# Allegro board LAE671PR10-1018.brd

Outline 297.76 x 76 mm; copper layers: TOP, IN1, GND1, IN2, GND2, VCC, IN3, GND3, IN4, BOTTOM. Coordinates in mm from the lower left corner of the outline.
Outline path: 0,73.65 arc(0.15,74) 0.5,74.15 7.13,74.15 arc(7.48,74) 7.63,73.65 7.63,69.3 arc(7.78,68.95) 8.13,68.8 26.13,68.8 arc(26.48,68.95) 26.63,69.3 26.63,75.5 arc(26.78,75.85) 27.13,76 172.13,76 arc(172.48,75.85) 172.63,75.5 172.63,35.05 arc(189.44,12.9) 215.3,23.12 arc(215.48,23.3) 215.72,23.36 220.66,23.36 arc(220.9,23.3) 221.08,23.12 arc(246.94,12.9) 263.75,35.05 263.75,68.3 arc(263.9,68.65) 264.25,68.8 287.63,68.8 arc(287.98,68.95) 288.13,69.3 288.13,71.49 arc(288.28,71.84) 288.63,71.99 297.26,71.99 arc(297.61,71.84) 297.76,71.49 297.76,69.37 arc(297.69,69.12) 297.51,68.93 arc(297.33,68.75) 297.26,68.5 297.26,53.8 arc(297.11,53.45) 296.76,53.3 arc(296.41,53.15) 296.26,52.8 296.26,47.8 arc(296.41,47.45) 296.76,47.3 arc(297.11,47.15) 297.26,46.8 297.26,44.94 arc(297.22,44.75) 297.11,44.58 295.83,43.3 arc(295.72,43.13) 295.68,42.94 295.68,41.36 arc(295.72,41.17) 295.83,41 297.11,39.72 arc(297.22,39.55) 297.26,39.36 297.26,2.5 arc(297.11,2.15) 296.76,2 274.93,2 arc(274.58,1.85) 274.43,1.5 274.43,0.5 arc(274.28,0.15) 273.93,0 180.83,0 180.83,1 172.63,1 172.63,0 86.89,0 arc(85.48,0.59) 84.89,2 arc(84.6,2.71) 83.89,3 81.89,3 arc(81.18,2.71) 80.89,2 80.89,1 arc(80.6,0.29) 79.89,0 23.33,0 arc(22.98,0.15) 22.83,0.5 22.83,1.5 arc(22.68,1.85) 22.33,2 0.5,2 arc(0.15,2.15) 0,2.5 0,30.05 arc(0.15,30.4) 0.5,30.55 2,30.55 arc(2.35,30.7) 2.5,31.05 2.5,35.55 arc(2.35,35.9) 2,36.05 0.5,36.05 arc(0.15,36.2) 0,36.55 0,43.22 arc(0.15,43.57) 0.5,43.72 arc(0.85,43.87) 1,44.22 1,49.22 arc(0.85,49.57) 0.5,49.72 arc(0.15,49.87) 0,50.22 0,51.98 arc(0.04,52.17) 0.15,52.34 1.45,53.64 arc(1.56,53.81) 1.6,54 1.6,55.88 arc(1.56,56.07) 1.45,56.24 0.15,57.54 arc(0.04,57.71) 0,57.9 0,59.67 arc(0.15,60.02) 0.5,60.17 arc(0.85,60.32) 1,60.67 1,65.67 arc(0.85,66.02) 0.5,66.17 arc(0.15,66.32) 0,66.67 0,73.65

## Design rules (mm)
net group 12C-15/15: nets PCH_SPI_CLK_R TBT_I2C_CLK
net group AMP_I2C_SM: nets AMP_I2C_CLK AMP_I2C_DAT
net group AMP_I2C_SM_R: nets AMP_I2C_CLK_R AMP_I2C_DAT_R
net group BOT_MUX__R: nets BOT_MUX_N_R BOT_MUX_P_R
net group CHG_CSI: nets CHG_CSIN CHG_CSIP
net group CHG_CSO: nets CHG_CSON CHG_CSOP
net group CL_SM: nets CL_CLK CL_DAT
net group DDI2_PTX_TBRX_1_C: nets DDI2_PTX_TBRX_N1_C DDI2_PTX_TBRX_P1_C
net group DDI2_PTX_TBRX_3_C: nets DDI2_PTX_TBRX_N3_C DDI2_PTX_TBRX_P3_C
net group DDI2_PTX_TBRX_N0_C: nets DDI2_PTX_TBRX_N0_C DDI2_PTX_TBRX_P0_C
net group DDI2_PTX_TBRX_N2_C: nets DDI2_PTX_TBRX_N2_C DDI2_PTX_TBRX_P2_C
net group DDR_XDP_SMBSM: nets DDR_XDP_SMBCLK DDR_XDP_SMBDAT
net group EC_I2C_SM: nets EC_I2C_CLK EC_I2C_DAT
net group EDP_AUX_C: nets EDP_AUXN_C EDP_AUXP_C
net group GT_SENSE: nets VCCGT_SENSE VSSGT_SENSE
net group HDA: nets HDA_BIT_CLK HDA_BIT_CLK_R
net group I2C1_SM: nets I2C1_SCK I2C1_SDA
net group I2C1_SM_TP: nets I2C1_SCK_TP I2C1_SDA_TP
net group ISUM_GT: nets ISUMN_GT ISUMP_GT
net group ISUM_SA: nets ISUMN_SA ISUMP_SA
net group ISUM_VCORE: nets ISUMN_VCORE ISUMP_VCORE
net group MEM_SMBSM: nets MEM_SMBCLK MEM_SMBDATA
net group MUX_C_AUX_: nets MUX_C_AUX_N MUX_C_AUX_P
net group MUX_I2C_SM_R: nets MUX_I2C_CLK_R MUX_I2C_DATA_R
net group MUX_USB3_TX0__C: nets MUX_USB3_TX0_N_C MUX_USB3_TX0_P_C
net group MUX_USB3_TX1__C: nets MUX_USB3_TX1_N_C MUX_USB3_TX1_P_C
net group PBAT_CHARGER_SMBSM: nets PBAT_CHARGER_SMBCLK PBAT_CHARGER_SMBDAT
net group PCIE_PRX_CARDTX_1: nets PCIE_PRX_CARDTX_N1 PCIE_PRX_CARDTX_P1
net group PCIE_PRX_CARDTX_1_C: nets PCIE_PRX_CARDTX_N1_C PCIE_PRX_CARDTX_P1_C
net group PCIE_PRX_TBTX_5: nets PCIE_PRX_TBTX_N5 PCIE_PRX_TBTX_P5
net group PCIE_PRX_TBTX_5_C: nets PCIE_PRX_TBTX_N5_C PCIE_PRX_TBTX_P5_C
net group PCIE_PRX_TBTX_6: nets PCIE_PRX_TBTX_N6 PCIE_PRX_TBTX_P6
net group PCIE_PRX_TBTX_6_C: nets PCIE_PRX_TBTX_N6_C PCIE_PRX_TBTX_P6_C
net group PCIE_PRX_TBTX_7: nets PCIE_PRX_TBTX_N7 PCIE_PRX_TBTX_P7
net group PCIE_PRX_TBTX_7_C: nets PCIE_PRX_TBTX_N7_C PCIE_PRX_TBTX_P7_C
net group PCIE_PRX_TBTX_8: nets PCIE_PRX_TBTX_N8 PCIE_PRX_TBTX_P8
net group PCIE_PRX_TBTX_8_C: nets PCIE_PRX_TBTX_N8_C PCIE_PRX_TBTX_P8_C
net group PCIE_PRX_WLANTX_3: nets PCIE_PRX_WLANTX_N3 PCIE_PRX_WLANTX_P3
net group PCIE_PRX_WLANTX_3_C: nets PCIE_PRX_WLANTX_N3_C PCIE_PRX_WLANTX_P3_C
net group PCIE_PTX_CARDRX_1: nets PCIE_PTX_CARDRX_N1 PCIE_PTX_CARDRX_P1
net group PCIE_PTX_CARDRX_1_C: nets PCIE_PTX_CARDRX_N1_C PCIE_PTX_CARDRX_P1_C
net group PCIE_PTX_TBRX_5: nets PCIE_PTX_TBRX_N5 PCIE_PTX_TBRX_P5
net group PCIE_PTX_TBRX_5_C: nets PCIE_PTX_TBRX_N5_C PCIE_PTX_TBRX_P5_C
net group PCIE_PTX_TBRX_6: nets PCIE_PTX_TBRX_N6 PCIE_PTX_TBRX_P6
net group PCIE_PTX_TBRX_6_C: nets PCIE_PTX_TBRX_N6_C PCIE_PTX_TBRX_P6_C
net group PCIE_PTX_TBRX_7: nets PCIE_PTX_TBRX_N7 PCIE_PTX_TBRX_P7
net group PCIE_PTX_TBRX_7_C: nets PCIE_PTX_TBRX_N7_C PCIE_PTX_TBRX_P7_C
net group PCIE_PTX_TBRX_8: nets PCIE_PTX_TBRX_N8 PCIE_PTX_TBRX_P8
net group PCIE_PTX_TBRX_8_C: nets PCIE_PTX_TBRX_N8_C PCIE_PTX_TBRX_P8_C
net group PCIE_PTX_WLANRX_3: nets PCIE_PTX_WLANRX_N3 PCIE_PTX_WLANRX_P3
net group PCIE_PTX_WLANRX_3_C: nets PCIE_PTX_WLANRX_N3_C PCIE_PTX_WLANRX_P3_C
net group PWR_MONITOR__SMBSM: nets PWR_MONITOR_SMBCLK PWR_MONITOR_SMBDAT
net group PWR_MONITOR_EC_SMBSM: nets PWR_MONITOR_EC_SMBCLK PWR_MONITOR_EC_SMBDAT
net group REM_DIODE4: nets REM_DIODE4_N REM_DIODE4_P
net group S_SENSE: nets VCC_SENSE VSS_SENSE
net group SA_SENSE: nets VCCSA_SENSE VSSSA_SENSE
net group SATA_PRX_SSDTX_2_C: nets SATA_PRX_SSDTX_N2_C SATA_PRX_SSDTX_P2_C
net group SATA_PTX_SSDRX_2_C: nets SATA_PTX_SSDRX_N2_C SATA_PTX_SSDRX_P2_C
net group SD_LN0_: nets SD_LN0_M SD_LN0_P
net group SD_LN1_: nets SD_LN1_M SD_LN1_P
net group SD_RCLK_: nets SD_RCLK_M SD_RCLK_P
net group SM_TP_SIO: nets CLK_TP_SIO DAT_TP_SIO
net group SMBUS: nets CLK_SMB DAT_SMB
net group SML1_SMBSM: nets SML1_SMBCLK SML1_SMBDAT
net group TBT_A_I2C_B__R: nets TBT_A_I2C_B_N_R TBT_A_I2C_B_P_R
net group TBT_A_USB2_T__R: nets TBT_A_USB2_T_N_R TBT_A_USB2_T_P_R
net group TBT_B_I2C_B__R: nets TBT_B_I2C_B_N_R TBT_B_I2C_B_P_R
net group TBT_B_USB2_T__R: nets TBT_B_USB2_T_N_R TBT_B_USB2_T_P_R
net group TOP_MUX__R: nets TOP_MUX_N_R TOP_MUX_P_R
net group UPD1_SMBSM: nets UPD1_SMBCLK UPD1_SMBDAT
net group UPD2_SMBSM: nets UPD2_SMBCLK UPD2_SMBDAT
net group UPD3_SMBSM: nets UPD3_SMBCLK UPD3_SMBDAT
net group USB20_7: nets USB20_N7 USB20_P7
net group USB20_7_CONN: nets USB20_N7_CONN USB20_P7_CONN
net group USB20_10: nets USB20_N10 USB20_P10
net group USB20_10_CONN: nets USB20_N10_CONN USB20_P10_CONN
net group 24MHZ: nets PCI_CLK_LPC1
net group 85H-TBT: nets TBT_USB3_RX0_N TBT_USB3_RX0_P TBT_USB3_RX1_N TBT_USB3_RX1_P TBT_USB3_RX2_N TBT_USB3_RX2_P TBT_USB3_RX3_N TBT_USB3_RX3_P TBT_USB3_TX0_N TBT_USB3_TX0_N_C TBT_USB3_TX0_P TBT_USB3_TX0_P_C TBT_USB3_TX1_N TBT_USB3_TX1_N_C TBT_USB3_TX1_P TBT_USB3_TX1_P_C TBT_USB3_TX2_N TBT_USB3_TX2_N_C TBT_USB3_TX2_P TBT_USB3_TX2_P_C TBT_USB3_TX3_N TBT_USB3_TX3_N_C TBT_USB3_TX3_P TBT_USB3_TX3_P_C
net group CLK-15/15: nets CLKREQ_PCIE#0 CLKREQ_PCIE#1 CLKREQ_PCIE#3 CLKREQ_PCIE#5
net group CLK-DF-12/15: nets CLK_ITPXDP_N CLK_ITPXDP_N_R CLK_ITPXDP_P CLK_ITPXDP_P_R
net group COMP: nets EDP_COMP PCIE_RCOMPN PCIE_RCOMPP USBCOMP
net group CRYSTAL: nets PCH_RTCX1 PCH_RTCX2 XTAL24_IN_RU XTAL24_OUT_RU
net group DDR-SINGLE: nets +V_DDR_REF_CA +V_DDR_REFA_R +V_DDR_REFB_R
net group DDR_DQS: nets DDR_A_DQS0 DDR_A_DQS1 DDR_A_DQS2 DDR_A_DQS3 DDR_A_DQS4 DDR_A_DQS5 DDR_A_DQS6 DDR_A_DQS7 DDR_A_DQS#0 DDR_A_DQS#1 DDR_A_DQS#2 DDR_A_DQS#3 DDR_A_DQS#4 DDR_A_DQS#5 DDR_A_DQS#6 DDR_A_DQS#7 DDR_B_DQS0 DDR_B_DQS1 DDR_B_DQS2 DDR_B_DQS3 DDR_B_DQS4 DDR_B_DQS5 DDR_B_DQS6 DDR_B_DQS7 DDR_B_DQS#0 DDR_B_DQS#1 DDR_B_DQS#2 DDR_B_DQS#3 DDR_B_DQS#4 DDR_B_DQS#5 DDR_B_DQS#6 DDR_B_DQS#7
net group DDRA-CLK: nets DDR_A_CLK0 DDR_A_CLK1 DDR_A_CLK#0 DDR_A_CLK#1
net group DDRA-CMD: nets DDR_A_CA1_0 DDR_A_CA1_1 DDR_A_CA1_2 DDR_A_CA1_3 DDR_A_CA1_4 DDR_A_CA1_5 DDR_A_CA1_6 DDR_A_CA1_7 DDR_A_CA1_8 DDR_A_CA1_9 DDR_A_CA2_0 DDR_A_CA2_1 DDR_A_CA2_2 DDR_A_CA2_3 DDR_A_CA2_4 DDR_A_CA2_5 DDR_A_CA2_6 DDR_A_CA2_7 DDR_A_CA2_8 DDR_A_CA2_9
net group DDRA-CTL: nets DDR_A_CS#0 DDR_A_CS#1 DDR_A_ODT0
net group DDRA-D0: nets DDR_A_D0 DDR_A_D1 DDR_A_D2 DDR_A_D3 DDR_A_D4 DDR_A_D5 DDR_A_D6 DDR_A_D7
net group DDRA-D1: nets DDR_A_D8 DDR_A_D9 DDR_A_D10 DDR_A_D11 DDR_A_D12 DDR_A_D13 DDR_A_D14 DDR_A_D15
net group DDRA-D2: nets DDR_A_D16 DDR_A_D17 DDR_A_D18 DDR_A_D19 DDR_A_D20 DDR_A_D21 DDR_A_D22 DDR_A_D23
net group DDRA-D3: nets DDR_A_D24 DDR_A_D25 DDR_A_D26 DDR_A_D27 DDR_A_D28 DDR_A_D29 DDR_A_D30 DDR_A_D31
net group DDRA-D4: nets DDR_A_D32 DDR_A_D33 DDR_A_D34 DDR_A_D35 DDR_A_D36 DDR_A_D37 DDR_A_D38 DDR_A_D39
net group DDRA-D5: nets DDR_A_D40 DDR_A_D41 DDR_A_D42 DDR_A_D43 DDR_A_D44 DDR_A_D45 DDR_A_D46 DDR_A_D47
net group DDRA-D6: nets DDR_A_D48 DDR_A_D49 DDR_A_D50 DDR_A_D51 DDR_A_D52 DDR_A_D53 DDR_A_D54 DDR_A_D55
net group DDRA-D7: nets DDR_A_D56 DDR_A_D57 DDR_A_D58 DDR_A_D59 DDR_A_D60 DDR_A_D61 DDR_A_D62 DDR_A_D63
net group DDRA_CKE: nets DDR_A_CKE0 DDR_A_CKE1 DDR_A_CKE2 DDR_A_CKE3
net group DDRB-CLK: nets DDR_B_CLK0 DDR_B_CLK1 DDR_B_CLK#0 DDR_B_CLK#1
net group DDRB-CMD: nets DDR_B_CA1_0 DDR_B_CA1_1 DDR_B_CA1_2 DDR_B_CA1_3 DDR_B_CA1_4 DDR_B_CA1_5 DDR_B_CA1_6 DDR_B_CA1_7 DDR_B_CA1_8 DDR_B_CA1_9 DDR_B_CA2_0 DDR_B_CA2_1 DDR_B_CA2_2 DDR_B_CA2_3 DDR_B_CA2_4 DDR_B_CA2_5 DDR_B_CA2_6 DDR_B_CA2_7 DDR_B_CA2_8 DDR_B_CA2_9
net group DDRB-CTL: nets DDR_B_CS#0 DDR_B_CS#1 DDR_B_ODT0
net group DDRB-D0: nets DDR_B_D0 DDR_B_D1 DDR_B_D2 DDR_B_D3 DDR_B_D4 DDR_B_D5 DDR_B_D6 DDR_B_D7
net group DDRB-D1: nets DDR_B_D8 DDR_B_D9 DDR_B_D10 DDR_B_D11 DDR_B_D12 DDR_B_D13 DDR_B_D14 DDR_B_D15
net group DDRB-D2: nets DDR_B_D16 DDR_B_D17 DDR_B_D18 DDR_B_D19 DDR_B_D20 DDR_B_D21 DDR_B_D22 DDR_B_D23
net group DDRB-D3: nets DDR_B_D24 DDR_B_D25 DDR_B_D26 DDR_B_D27 DDR_B_D28 DDR_B_D29 DDR_B_D30 DDR_B_D31
net group DDRB-D4: nets DDR_B_D32 DDR_B_D33 DDR_B_D34 DDR_B_D35 DDR_B_D36 DDR_B_D37 DDR_B_D38 DDR_B_D39
net group DDRB-D5: nets DDR_B_D40 DDR_B_D41 DDR_B_D42 DDR_B_D43 DDR_B_D44 DDR_B_D45 DDR_B_D46 DDR_B_D47
net group DDRB-D6: nets DDR_B_D48 DDR_B_D49 DDR_B_D50 DDR_B_D51 DDR_B_D52 DDR_B_D53 DDR_B_D54 DDR_B_D55
net group DDRB-D7: nets DDR_B_D56 DDR_B_D57 DDR_B_D58 DDR_B_D59 DDR_B_D60 DDR_B_D61 DDR_B_D62 DDR_B_D63
net group DDRB_CKE: nets DDR_B_CKE0 DDR_B_CKE1 DDR_B_CKE2 DDR_B_CKE3
net group DDRRCOMP-20/25: nets SM_RCOMP0 SM_RCOMP1 SM_RCOMP2
net group DP-AR: nets TBT_DP_AUX_N TBT_DP_AUX_N_C TBT_DP_AUX_P TBT_DP_AUX_P_C TBT_DP_ML0_N TBT_DP_ML0_N_C TBT_DP_ML0_P TBT_DP_ML0_P_C TBT_DP_ML1_N TBT_DP_ML1_N_C TBT_DP_ML1_P TBT_DP_ML1_P_C TBT_DP_ML2_N TBT_DP_ML2_N_C TBT_DP_ML2_P TBT_DP_ML2_P_C TBT_DP_ML3_N TBT_DP_ML3_N_C TBT_DP_ML3_P TBT_DP_ML3_P_C
net group DP-DDI1: nets CPU_DDI1_AUXN CPU_DDI1_AUXN_C CPU_DDI1_AUXP CPU_DDI1_AUXP_C DDI1_PTX_TBRX_N0 DDI1_PTX_TBRX_N0_C DDI1_PTX_TBRX_N1 DDI1_PTX_TBRX_N1_C DDI1_PTX_TBRX_N2 DDI1_PTX_TBRX_N2_C DDI1_PTX_TBRX_N3 DDI1_PTX_TBRX_N3_C DDI1_PTX_TBRX_P0 DDI1_PTX_TBRX_P0_C DDI1_PTX_TBRX_P1 DDI1_PTX_TBRX_P1_C DDI1_PTX_TBRX_P2 DDI1_PTX_TBRX_P2_C DDI1_PTX_TBRX_P3 DDI1_PTX_TBRX_P3_C
net group DP-DDI2: nets CPU_DDI2_AUXN CPU_DDI2_AUXN_C CPU_DDI2_AUXP CPU_DDI2_AUXP_C DDI2_PTX_TBRX_N0 DDI2_PTX_TBRX_N1 DDI2_PTX_TBRX_N2 DDI2_PTX_TBRX_N3 DDI2_PTX_TBRX_P0 DDI2_PTX_TBRX_P1 DDI2_PTX_TBRX_P2 DDI2_PTX_TBRX_P3
net group EDP: nets EDP_AUXN EDP_AUXN_CONN EDP_AUXP EDP_AUXP_CONN EDP_TXN_P0 EDP_TXN_P0_C EDP_TXN_P0_CONN EDP_TXN_P1 EDP_TXN_P1_C EDP_TXN_P1_CONN EDP_TXN_P2 EDP_TXN_P2_C EDP_TXN_P2_CONN EDP_TXN_P3 EDP_TXN_P3_C EDP_TXN_P3_CONN EDP_TXP_P0 EDP_TXP_P0_C EDP_TXP_P0_CONN EDP_TXP_P1 EDP_TXP_P1_C EDP_TXP_P1_CONN EDP_TXP_P2 EDP_TXP_P2_C EDP_TXP_P2_CONN EDP_TXP_P3 EDP_TXP_P3_C EDP_TXP_P3_CONN
net group HDA-5/5: nets HDA_SDIN0 HDA_SDIN0_R HDA_SDOUT HDA_SDOUT_R HDA_SYNC HDA_SYNC_R
net group I2C: nets CL_CLK_R CL_DAT_R DCI_CLK DCI_DATA I2C0_SCK_TS I2C0_SDA_TS I2C2_SCK_EDP_PCH I2C2_SDA_EDP_PCH PWR_MONITOR_I2CCLK PWR_MONITOR_I2CSDA
net group I2C_5: nets TBT_I2C_DATA
net group PCIE: nets PCIE_PRX_SSDTX_N9 PCIE_PRX_SSDTX_N10 PCIE_PRX_SSDTX_N11 PCIE_PRX_SSDTX_P9 PCIE_PRX_SSDTX_P10 PCIE_PRX_SSDTX_P11 PCIE_PTX_SSDRX_N9 PCIE_PTX_SSDRX_N9_C PCIE_PTX_SSDRX_N10 PCIE_PTX_SSDRX_N10_C PCIE_PTX_SSDRX_N11 PCIE_PTX_SSDRX_N11_C PCIE_PTX_SSDRX_P9 PCIE_PTX_SSDRX_P9_C PCIE_PTX_SSDRX_P10 PCIE_PTX_SSDRX_P10_C PCIE_PTX_SSDRX_P11 PCIE_PTX_SSDRX_P11_C SATA_PRX_SSDTX_N2 SATA_PRX_SSDTX_P2 SATA_PTX_SSDRX_N2 SATA_PTX_SSDRX_P2
net group PCIE_CLK: nets CLK0_PCIE_TBT CLK0_PCIE_TBT# CLK1_PCIE_WLAN CLK1_PCIE_WLAN# CLK_PCIE_MMI CLK_PCIE_MMI# CLK_PCIE_SSD CLK_PCIE_SSD#
net group RESET: nets PCH_RTCRST#
net group S-5/5: nets +3.3VDX_SSD +3.3VDX_SSD_IN+ +3VS_NGFF +3VS_NGFF_IN+ +INV_PWR_SRC +INV_PWR_SRC_IN+ +LCDVDD +LCDVDD_IN+ ESPI_ALERT# ESPI_CS# ESPI_IO0 ESPI_IO0_R ESPI_IO1 ESPI_IO1_R ESPI_IO2 ESPI_IO2_R ESPI_IO3 ESPI_IO3_R
net group S-8/8: nets H_CATERR# H_PROCHOT# H_PROCHOT#_R H_PROCHOT#_R1 H_VCCST_PWRGD_P VCCST_PWRGD
net group S-10/10: nets CL_RST# CL_RST#_R ESPI_RESET# JTAG_RST# MSDATA MUX_C_RESET_N PCH_RSMRST# PM_SYS_RESET# RESET_OUT#_R RTCRST_ON TBT_A_RESET_N TBT_B_RESET_N TBT_RESET_N_EC TBT_RESET_N_EC_R TBT_RESET_N_R UPD_MRESET
net group S-12/12: nets H_VCCST_PWRGD
net group S-15/15: nets AMP_I2S_MCLK AMP_I2S_MCLK_R CSI2_COMP EMMC_RCOMP ESPI_CLK_5105 MSCLK PCH_PLTRST# PCH_PLTRST#_5105 PCH_PLTRST#_EC PCH_RTCX2_R PCI_CLK_LPC0 SD_CLK SD_CLK_L SD_RCOMP SRTCRST# SUSCLK SYS_RESET# SYS_RESET#_R TBT_PERST_N TBT_ROM_CLK VCC_EDRAM_SENSE VIDSCLK_R VIDSOUT_R VR_SVID_CLK VR_SVID_CLK_C VR_SVID_DATA VR_SVID_DATA_C VSS_EDRAM_SENSE XCLK_BIASREF XDP_TCK0 XDP_TCK1 XTAL24_IN XTAL24_OUT XTAL_25_IN XTAL_25_OUT XTAL_25_OUT_R
net group S-18/18: nets EOPIO_RCOMP H_CPU_SVIDALRT# H_THERMTRIP# H_THERMTRIP#_R PECI_EC PECI_EC_R VR_SVID_ALERT# VR_SVID_ALERT#_C
net group S-20/20: nets +VREFCA +VREFDQ_A +VREFDQ_B CFG_RCOMP CPU_POPIRCOMP EDRAM_OPIO_RCOMP MEC_XTAL1 MEC_XTAL2 MEC_XTAL2_R N40373163 N40373501 N40376778 PCH_POPIRCOMP
net group SENSE: nets VCC_EOPIO_SENSE VCCIO_SENSE VSS_EOPIO_SENSE VSSIO_SENSE
net group SPI: nets PCH_SPI_CLK PCH_SPI_CLK_TPM PCH_SPI_CS2# PCH_SPI_IO2 PCH_SPI_IO3 PCH_SPI_SI PCH_SPI_SI_TPM PCH_SPI_SO PCH_SPI_SO_TPM SPI_CLK_VROM TPM_PIRQ#
net group SPI-5/5: nets CFG0 CFG1 CFG2 CFG3 CFG4 CFG5 CFG6 CFG7 CFG8 CFG9 CFG10 CFG11 CFG12 CFG13 CFG14 CFG15 CFG16 CFG17 CFG18 CFG19 CPU_XDP_PRDY# PCH_SPI_CS0# PCH_SPI_CS0#_R PCH_SPI_IO2_R PCH_SPI_IO3_R PCH_SPI_SI_R PCH_SPI_SO_R PWRGD_XDP SPI_IO2_VROM SPI_IO3_VROM SPI_SI_VROM SPI_SO_VROM XDP_PIN1 XDP_PRSENT# XDP_PWRBTN#
net group TBT PORT A: nets TBT_A_AUX_N TBT_A_AUX_N_C TBT_A_AUX_P TBT_A_AUX_P_C TBT_A_LSRX TBT_A_LSRX_R TBT_A_LSTX TBT_A_LSTX_R
net group TBT PORT B: nets TBT_B_AUX_N TBT_B_AUX_N_C TBT_B_AUX_P TBT_B_AUX_P_C TBT_B_LSRX TBT_B_LSRX_R TBT_B_LSTX TBT_B_LSTX_R
net group THERMAL: nets REM_DIODE1_N REM_DIODE1_P REM_DIODE2_N REM_DIODE2_P REM_DIODE3_N REM_DIODE3_P
net group USB2.0: nets BOT_MUX_N BOT_MUX_P TBT_A_I2C_B_N TBT_A_I2C_B_P TBT_A_USB2_D_N TBT_A_USB2_D_P TBT_A_USB2_T_N TBT_A_USB2_T_P TBT_B_I2C_B_N TBT_B_I2C_B_P TBT_B_USB2_D_N TBT_B_USB2_D_P TBT_B_USB2_T_N TBT_B_USB2_T_P TOP_MUX_N TOP_MUX_P USB20_N1 USB20_N5 USB20_N5_CONN USB20_P1 USB20_P5 USB20_P5_CONN
net group USB3.0: nets MUX_USB3_RX0_N MUX_USB3_RX0_P MUX_USB3_RX1_N MUX_USB3_RX1_P MUX_USB3_TX0_N MUX_USB3_TX0_P MUX_USB3_TX1_N MUX_USB3_TX1_P USB3RN1 USB3RN1_C USB3RP1 USB3RP1_C USB3TN1 USB3TN1_C USB3TP1 USB3TP1_C
net group W10: nets DMIC_CLK_CODEC DMIC_CLK_CODEC_R DMIC_DAT12_CODEC DMIC_DAT12_CODEC_R DMIC_DAT34_CODEC DMIC_DAT34_CODEC_R HP2_D_L HP2_D_L_C HP2_D_L_R1 HP2_D_R HP2_D_R_C HP2_D_R_R1 LINE1_L LINE1_L_C LINE1_R LINE1_R_C MIC2_VREFO_L
net group W20: nets +1.8VA +3VA_TBT +3VLP +3VS_AUDIO +3VS_TP +AVDD1 +AVDD2 +DVDD +RTCVCC ALW_PWRGD_3V_5V TBT_A_CC1 TBT_A_CC2 TBT_B_CC1 TBT_B_CC2
net group W40: nets AMP_OUT_L+ AMP_OUT_L- AMP_OUT_R+ AMP_OUT_R- MIC2_VREFO_R RING2 RING2_R SLEEVE SLEEVE_R SPK_OUT_L+ SPK_OUT_L+_R SPK_OUT_L- SPK_OUT_L-_R SPK_OUT_R+ SPK_OUT_R+_R SPK_OUT_R- SPK_OUT_R-_R
net group XDP-JTAG: nets CPU_XDP_PREQ# CPU_XDP_TCK CPU_XDP_TDI CPU_XDP_TDO CPU_XDP_TMS PCH_JTAG_TCK PCH_JTAG_TDI PCH_JTAG_TDO PCH_JTAG_TMS PCH_JTAG_TRST# PCH_JTAGX
net group XDP-SINGLE: nets CPU_XDP_TRST# XDP_DBRESET# XDP_RST# XDP_TRST#
nets with their own width: min track width 0.254; nets +3V_VC_A +3V_VC_B +3V_VC_C
nets with their own width: min track width 0.508; nets +0.6VSP +1.0V_AMPHYPLL +1.0V_APLL +1.0V_APLLEBB +1.0V_CLK +1.0V_DTS +1.0V_MPHYAON +1.0V_VCCST +1.0V_VCCSTG +1.0V_VCCSTG_R +1.0VA_XDP +1.2V_MEM_CPUCLK +1.8V_3.3V_ALW_VTR3 +1.8V_PGPP +1.8VS_AUDIO +3.3V_EC5105 +3.3V_EC_PLL +3.3V_PGPP +3.3V_SPI +3V_LDO +3V_LDOP +3V_PCH_DSW +3VA_TBT_LC +3VALW +3VALWP +3VS_MUX +3VS_TPM +3VS_TS +5VALW +5VALWP +8.4V_BATT+ +BATT +DVDDIO +EC_DEBUG_VCC +ODR_PWR +PECI_VREF +RTC_CELL_VBAT +RTCBATT +SD_VDD2 +TPM_LPM +V1.8S_EDRAM +VCC0V9_CIO +VCC0V9_DP +VCC0V9_PCIE +VCC0V9_USB +VCC_CORE +VCC_CORE_G0 +VCC_CORE_G1 +VCC_EDRAM +VCC_EDRAM_P +VCC_EOPIO +VCCGT +VCCPLL_OC +VR_CAP +VSS_PLL
nets with their own width: min track width 0.635; nets +0.6VS +1.0V_SRAM +1.8VU +1.8VUP +3VS_CAM
nets with their own width: min track width 0.762; nets +3V_TBT_S0 +5VS +5VS_AUDIO
nets with their own width: min track width 0.889; nets +3V_TBT
nets with their own width: min track width 1.016; nets +1.8VAP +3V_PCH B+_AMP
nets with their own width: min track width 1.27; nets +PVDD2
nets with their own width: min track width 1.651; nets +3VS_CR
nets with their own width: min track width 2.032; nets +VCC_EOPIO_P
nets with their own width: min track width 2.54; nets +3VS
nets with their own width: min track width 2.667; nets +1.0V_PRIM_CORE +1.0V_PRIM_COREP
nets with their own width: min track width 2.794; nets +1.0V_MPHYGT
nets with their own width: min track width 3.048; nets +BAT_TABLET +CHG_SRC_20V +CHG_VIN_20V +VBUS1_20V +VBUS1_PD_20V +VBUS2_20V +VBUS2_PD_20V +VBUS3_20V +VBUS3_PD_20V TBT_A_VBUS_L TBT_B_VBUS_L
nets with their own width: min track width 3.175; nets +1.0VS_VCCIO +1.0VS_VCCIOP
nets with their own width: min track width 3.429; nets +1.0VA +1.0VAP
nets with their own width: min track width 4.572; nets +1.2V_DDR +1.2V_DDRP +VCCSA

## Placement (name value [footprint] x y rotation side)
C18  10U_0402_6.3V6M  [C_0402]  282.87 28.4 90 bottom
C19  0.1U_0201_10V6K  [C_0201]  281.21 27.72 90 bottom
C20  0.1U_0201_10V6K  [C_0201]  280.62 27.73 90 bottom
C21  68P_0402_50V8J  [C_0402]  283.76 28.4 90 bottom
C27  0.1U_0201_10V6K  [C_0201]  172.54 17.62 0 bottom
C28  0.1U_0201_10V6K  [C_0201]  175.55 13.1 270 bottom
C29  0.1U_0201_10V6K  [C_0201]  176.11 13.1 270 bottom
C30  10U_0603_6.3V6M  [C_0603]  172.79 18.69 90 bottom
C31  0.1U_0201_10V6K  [C_0201]  167.81 15.49 270 bottom
C32  0.1U_0201_10V6K  [C_0201]  175.5 15.4 90 bottom
C33  0.1U_0402_10V7K  [C_0402]  271.84 55.74 90 bottom
C34  22U_0603_6.3V6M~D  [C_0603]  271.76 44.3 0 top
C35  15P_0402_50V8J  [C_0402]  270.95 55.76 90 bottom
C36  15P_0402_50V8J  [C_0402]  285.98 49.59 90 bottom
C37  15P_0402_50V8J  [C_0402]  285.98 48.76 270 bottom
C39  100P_0201_50V8J  [C_0201]  292.46 33.84 0 bottom
C40  22P_0402_50V8J  [C_0402]  284.22 33.64 180 bottom
C41  4.7U_0402_6.3V  [C_0402]  145.76 36.2 180 top
C42  .1U_0402_16V7K~D  [C_0402]  153.25 20.81 180 top
C43  0.01U_0402_16V7K~D  [C_0402]  153.25 19.92 180 top
C44  47P_0402_50V8J~D  [C_0402]  152.26 39.06 90 bottom
C45  15P_0402_50V8J  [C_0402]  153.15 39.06 90 bottom
C46  0.1U_0402  [C_0402]  265.57 7.3 270 bottom
C47  0.1U_0402  [C_0402]  210.4 4.59 0 bottom
C48  0.1U_0201_10V6K  [C_0201]  265.91 23.45 180 top
C49  0.1U_0201_10V6K  [C_0201]  271.65 20.96 0 top
C50  0.1U_0201_10V6K  [C_0201]  275.55 27.72 0 top
C51  0.01U_0402_16V7K  [C_0402]  275.5 28.49 0 top
C52  0.1U_0201_10V6K  [C_0201]  265.53 18.91 90 top
C53  0.1U_0201_10V6K  [C_0201]  266.29 18.91 90 top
C54  0.1U_0201_10V6K  [C_0201]  268.14 19.86 90 top
C55  0.1U_0201_10V6K  [C_0201]  271.59 27.92 90 top
C56  0.1U_0201_10V6K  [C_0201]  268.77 19.86 90 top
C57  0.1U_0201_10V6K  [C_0201]  271.02 27.92 90 top
C58  0.1U_0201_10V6K  [C_0201]  270.45 20.11 90 top
C59  0.1U_0201_10V6K  [C_0201]  271.02 20.11 90 top
C60  0.1U_0201_10V6K  [C_0201]  273.33 19.48 90 top
C61  0.1U_0201_10V6K  [C_0201]  273.9 19.48 90 top
C62  0.1U_0201_10V6K  [C_0201]  269.62 27.92 90 top
C63  0.1U_0201_10V6K  [C_0201]  270.19 27.92 90 top
C64  0.1U_0201_10V6K  [C_0201]  276.02 23 180 top
C65  0.1U_0201_10V6K  [C_0201]  276.02 24.08 180 top
C66  0.1U_0201_10V6K  [C_0201]  265.33 24.02 0 top
C67  0.1U_0201_10V6K  [C_0201]  265.33 24.6 0 top
C68  0.1U_0201_10V6K  [C_0201]  266.32 21.66 90 top
C69  0.1U_0201_10V6K  [C_0201]  265.6 21.66 90 top
C70  2.2U_0402_6.3V6M  [C_0402]  265.09 27.01 0 top
C71  0.1U_0402_10V7K  [C_0402]  7.99 32.89 90 top
C74  0.1U_0402_10V7K  [C_0402]  48.66 58.38 180 top
C76  1U_0402_6.3V6K~D  [C_0402]  48.64 64.04 180 top
C80  1U_0402_6.3V6K~D  [C_0402]  152.25 35.89 90 top
C81  1U_0402_6.3V6K~D  [C_0402]  221.53 7.14 270 top
C82  0.1U_0402_10V7K  [C_0402]  147.6 30.07 180 top
C83  1000P_0402_50V7K~D  [C_0402]  145.84 32.73 180 top
C84  2200P_0402_25V7K~D  [C_0402]  225.17 9.75 0 top
C85  0.1U_0402_10V7K  [C_0402]  225.62 12 180 top
C86  220P_0402_50V8K  [C_0402]  225.17 8.87 0 top
C87  2200P_0402_25V7K~D  [C_0402]  145.84 33.61 180 top
C88  1U_0402_6.3V6K~D  [C_0402]  151.88 31.53 180 top
C89  1U_0402_6.3V6K~D  [C_0402]  219.8 10.96 180 top
C90  0.1U_0402_10V7K  [C_0402]  149.39 36.27 0 top
C91  0.1U_0402_10V7K  [C_0402]  226.09 6.71 180 top
C92  1U_0402_6.3V6K~D  [C_0402]  266.69 49.41 180 top
C93  1U_0402_6.3V6K~D  [C_0402]  253.27 9.8 0 top
C94  2200P_0402_25V7K~D  [C_0402]  268.43 44.52 270 top
C95  0.1U_0402_10V7K  [C_0402]  270.58 43.26 180 top
C96  0.1U_0402_10V7K  [C_0402]  257.55 10.12 180 top
C97  1000P_0402_50V7K~D  [C_0402]  256 7.96 0 top
C98  4700P_0402_25V7K  [C_0402]  267.54 44.52 270 top
C99  4700P_0402_25V7K  [C_0402]  256 7.07 0 top
C100  1U_0402_6.3V6K~D  [C_0402]  269.61 49.46 0 top
C101  1U_0402_6.3V6K~D  [C_0402]  253.07 5.04 0 top
C102  0.1U_0402_10V7K  [C_0402]  267.5 42.7 0 top
C103  0.1U_0402_10V7K  [C_0402]  257.55 4.91 180 top
C104  0.1U_0402_10V7K  [C_0402]  45.38 56.67 270 bottom
C105  1U_0402_6.3V6K~D  [C_0402]  43.73 54.24 90 bottom
C106  1U_0402_6.3V6K  [C_0402]  281.98 28.4 90 bottom
C107  0.1U_0402_10V7K  [C_0402]  291.76 27.73 90 bottom
C121  1U_0402_6.3V6K~D  [C_0402]  177.51 10.75 0 bottom
C122  15P_0402_50V8J  [C_0402]  177.51 9.84 0 bottom
C123  680P_0402_50V7K~D  [C_0402]  167.12 7.32 180 bottom
C124  680P_0402_50V7K~D  [C_0402]  167.12 6.05 180 bottom
C131  10U_0402_6.3V6M  [C_0402]  49.54 53.6 90 bottom
C132  0.1U_0201_10V6K  [C_0201]  49.85 58.35 0 bottom
C133  0.1U_0201_10V6K  [C_0201]  49.85 57.77 0 bottom
C139  10U_0402_6.3V6M  [C_0402]  17.72 34.77 90 top
C140  1U_0603_25V6K  [C_0603]  13.93 23.91 180 top
C141  1U_0201_6.3V6M  [C_0201]  15.91 35.1 90 top
C142  10U_0402_6.3V6M  [C_0402]  18.66 34.88 90 top
C143  22U_0603_6.3V6M  [C_0603]  20.64 26.41 270 top
C144  22U_0603_6.3V6M  [C_0603]  23.08 26.41 270 top
C145  22U_0603_6.3V6M  [C_0603]  21.86 26.41 270 top
C146  22U_0603_6.3V6M  [C_0603]  17.46 26.22 270 top
C148  1U_0603_25V6K  [C_0603]  14.98 26.12 0 top
C149  220P_0402_50V8K  [C_0402]  17.31 28.2 90 bottom
C150  220P_0402_50V8K  [C_0402]  13.76 27.77 180 top
C151  0.22U_0201_6.3V6M  [C_0201]  13.54 28.53 180 top
C152  10U_0402_6.3V6M  [C_0402]  30.11 37 90 top
C153  1U_0603_25V6K  [C_0603]  26.51 24.9 180 top
C154  1U_0201_6.3V6M  [C_0201]  28.69 37 90 top
C155  10U_0402_6.3V6M  [C_0402]  31.21 37.12 90 top
C156  22U_0603_6.3V6M  [C_0603]  35.75 28.65 270 top
C157  22U_0603_6.3V6M  [C_0603]  33.31 28.65 270 top
C158  22U_0603_6.3V6M  [C_0603]  34.53 28.65 270 top
C159  22U_0603_6.3V6M  [C_0603]  29.63 28.33 270 top
C161  1U_0603_25V6K  [C_0603]  27.03 28.53 180 top
C162  220P_0402_50V8K  [C_0402]  28.77 30.49 270 bottom
C163  220P_0402_50V8K  [C_0402]  27.52 32.1 180 top
C164  0.22U_0201_6.3V6M  [C_0201]  26.75 30.56 180 top
C165  10U_0402_6.3V6M  [C_0402]  283.33 17.74 180 bottom
C166  1U_0603_25V6K  [C_0603]  295 14.13 180 top
C167  1U_0201_6.3V6M  [C_0201]  283.16 18.5 180 bottom
C168  10U_0402_6.3V6M  [C_0402]  283.23 16.71 180 bottom
C169  22U_0603_6.3V6M  [C_0603]  291.8 16.64 0 bottom
C170  22U_0603_6.3V6M  [C_0603]  291.8 15.44 0 bottom
C171  22U_0603_6.3V6M  [C_0603]  291.8 14.22 0 bottom
C172  22U_0603_6.3V6M  [C_0603]  291.8 13 0 bottom
C174  1U_0603_25V6K  [C_0603]  293.49 17.24 0 top
C175  220P_0402_50V8K  [C_0402]  289.09 20.5 90 bottom
C176  220P_0402_50V8K  [C_0402]  289.77 23.24 90 bottom
C177  0.22U_0201_6.3V6M  [C_0201]  286.52 21.39 180 bottom
C178  0.47U_0402_25V6K  [C_0402]  7.58 47.05 90 bottom
C179  0.47U_0402_25V6K  [C_0402]  8.46 47.05 90 bottom
C180  0.47U_0402_25V6K  [C_0402]  8.42 46.2 270 bottom
C181  0.47U_0402_25V6K  [C_0402]  7.53 46.2 270 bottom
C182  0.47U_0402_25V6K  [C_0402]  7.32 62.65 270 bottom
C183  0.47U_0402_25V6K  [C_0402]  8.21 62.65 270 bottom
C184  0.47U_0402_25V6K  [C_0402]  7.32 63.48 90 bottom
C185  0.47U_0402_25V6K  [C_0402]  8.21 63.48 90 bottom
C186  0.47U_0402_25V6K  [C_0402]  288.84 49.18 270 bottom
C187  0.47U_0402_25V6K  [C_0402]  288.84 50.04 90 bottom
C188  0.47U_0402_25V6K  [C_0402]  287.94 49.18 270 bottom
C189  0.47U_0402_25V6K  [C_0402]  287.94 50.04 90 bottom
C312  0.1U_0402_25V6K  [C_0402]  281.3 14.76 180 top
C375  0.1U_0402_25V6K~D  [C_0402]  23.52 9.67 0 bottom
C376  0.1U_0402_25V6K~D  [C_0402]  23.52 8.78 0 bottom
C377  0.1U_0402_25V6K~D  [C_0402]  23.79 7.84 270 bottom
C1018  100P_0201_50V8J  [C_0201]  42.75 58.25 180 bottom
C1049  22P_0201_25V8J  [C_0201]  279.45 26.13 180 top
C1050  0.1U_0201_10V6K  [C_0201]  283.27 18.36 0 top
C1051  1U_0603_25V6K  [C_0603]  284.76 15.51 90 top
C1052  0.1U_0402_25V6  [C_0402]  279.58 25.36 180 top
C1053  10U_0603_25V6M  [C_0603]  278.32 17.52 0 top
C1054  0.1U 16V K X5R 0201  [C_0201]  279.44 26.75 180 top
C1055  0.1U_0201_10V6K  [C_0201]  39.28 56.12 90 bottom
C1056  0.1U_0201_10V6K  [C_0201]  36.36 56.12 90 bottom
C1057  0.1U_0201_10V6K  [C_0201]  40.74 56.12 90 bottom
C1058  0.1U_0201_10V6K  [C_0201]  40.04 56.12 90 bottom
C1059  0.1U_0201_10V6K  [C_0201]  35.54 56.12 90 bottom
C1060  0.1U_0201_10V6K  [C_0201]  41.38 56.12 90 bottom
C1061  0.1U_0201_10V6K  [C_0201]  37 56.12 90 bottom
C1062  0.1U_0201_10V6K  [C_0201]  34.9 56.12 90 bottom
C1063  0.1U_0201_10V6K  [C_0201]  38.27 56.12 90 bottom
C1064  0.1U_0201_10V6K  [C_0201]  37.63 56.12 90 bottom
C1065  10U_0603_6.3V6M  [C_0603]  43.66 56.22 180 bottom
C1066  22P_0402_50V8J  [C_0402]  43.17 57.36 180 bottom
C1067  0.1U_0201_10V6K  [C_0201]  44.49 56.26 270 bottom
C1068  10U_0603_25V6M  [C_0603]  281.79 30.44 0 bottom
C1069  22P_0201_25V8J  [C_0201]  164.29 1.73 180 bottom
C1070  1U_0603_25V6K  [C_0603]  163.17 8.08 0 bottom
C1071  0.01UF_0402_25V7K  [C_0402]  161.71 3.08 270 bottom
C1072  0.1U_0402_25V6  [C_0402]  165.27 1.78 90 bottom
C1073  0.1U_0201_10V6K  [C_0201]  165.39 8.05 90 bottom
C1075  0.1U_0402_25V6K~D  [C_0402]  171.13 20.43 180 top
C1076  0.1U_0402_25V6K~D  [C_0402]  171.13 18.65 180 top
C1077  0.1U_0201_10V6K  [C_0201]  76.18 3.22 270 top
C1079  2.2U_0402_6.3V6M  [C_0402]  260.42 4.86 0 top
C1080  0.1U_0201_10V6K  [C_0201]  281.28 8.62 90 bottom
C1081  0.1U_0201_10V6K  [C_0201]  167.83 11.91 270 bottom
C1082  4.7U_0402_6.3V6M  [C_0402]  166.94 11.53 90 bottom
C1083  100P_0201_50V8J  [C_0201]  26.2 54.65 90 bottom
C1085  0.1U_0402_25V6  [C_0402]  7.63 40.1 270 top
C1086  0.1U_0402_25V6  [C_0402]  11.34 60.76 270 top
C1087  0.1U_0201_10V6K  [C_0201]  19.69 34.12 0 bottom
C1088  0.1U_0201_10V6K  [C_0201]  289.13 18.05 0 top
C1089  39P_0201_50V8J  [C_0201]  23.99 46.69 180 top
C1090  100P_0201_50V8J  [C_0201]  23.99 47.33 180 top
C1091  39P_0201_50V8J  [C_0201]  19.72 49.74 180 top
C1092  100P_0201_50V8J  [C_0201]  20.87 50.43 0 top
C1093  39P_0201_50V8J  [C_0201]  24.8 50.88 180 top
C1094  100P_0201_50V8J  [C_0201]  24.8 51.44 180 top
C1095  39P_0201_50V8J  [C_0201]  17.57 52.66 180 top
C1096  100P_0201_50V8J  [C_0201]  17.57 52.03 180 top
C1097  39P_0201_50V8J  [C_0201]  23.03 49.74 0 top
C1098  100P_0201_50V8J  [C_0201]  23.1 49.11 0 top
C1099  39P_0201_50V8J  [C_0201]  22.9 42.76 0 top
C1100  100P_0201_50V8J  [C_0201]  22.72 46.57 180 top
C1101  39P_0201_50V8J  [C_0201]  21.48 48.6 90 top
C1102  100P_0201_50V8J  [C_0201]  20.89 48.6 90 top
C1103  39P_0201_50V8J  [C_0201]  24.68 44.84 0 top
C1104  100P_0201_50V8J  [C_0201]  24.68 45.42 0 top
C1105  39P_0201_50V8J  [C_0201]  21.63 47.15 0 top
C1106  100P_0201_50V8J  [C_0201]  21.63 47.78 0 top
C1107  39P_0201_50V8J  [C_0201]  25.31 47.89 90 top
C1108  100P_0201_50V8J  [C_0201]  24.93 49.23 0 top
C1109  39P_0201_50V8J  [C_0201]  22.26 45.3 180 top
C1110  100P_0201_50V8J  [C_0201]  22.26 45.93 180 top
C1111  39P_0201_50V8J  [C_0201]  20.99 45.3 180 top
C1112  100P_0201_50V8J  [C_0201]  20.99 45.93 180 top
C1113  39P_0201_50V8J  [C_0201]  20.87 49.83 0 top
C1114  100P_0201_50V8J  [C_0201]  20.3 49.15 180 top
C1115  39P_0201_50V8J  [C_0201]  20.92 55.75 0 bottom
C1116  100P_0201_50V8J  [C_0201]  20.92 56.32 0 bottom
C1117  0.1U_0201_10V6K  [C_0201]  282.61 20.15 0 bottom
C1118  0.1U_0201_10V6K  [C_0201]  282.61 19.13 0 bottom
C1119  22P_0201_25V8J  [C_0201]  282.53 32.24 0 bottom
C1120  1U_0603_25V6K  [C_0603]  279.16 38.93 0 bottom
C1121  0.01UF_0402_25V7K  [C_0402]  277.95 34.32 0 bottom
C1122  0.1U_0402_25V6  [C_0402]  282.31 31.48 0 bottom
C1123  0.1U_0201_10V6K  [C_0201]  281.88 37.87 90 bottom
C1124  10U_0603_25V6M  [C_0603]  264.52 7.68 270 bottom
C1125  10U_0603_25V6M  [C_0603]  210.11 3.54 0 bottom
C1126  0.1U_0201_10V6K  [C_0201]  274.86 19.45 0 top
C1127  0.1U_0201_10V6K  [C_0201]  274.88 20.03 0 top
C1128  10U_0402_6.3V6M  [C_0402]  274.82 18.13 0 top
CA1  100P_0402_50V8J~D  [C_0402]  96.49 67.99 0 top
CA2  100P_0402_50V8J~D  [C_0402]  97.31 69.99 90 bottom
CA3  10U_0603_10V6M  [C_0603]  275.38 54.88 90 top
CA4  10U_0603_6.3V6M~D  [C_0603]  268.85 59.23 90 bottom
CA5  0.1U_0402_16V7K~N  [C_0402]  274.16 53.5 180 top
CA6  10U_0603_10V6M  [C_0603]  276.18 55.71 0 bottom
CA7  0.1U_0402_10V7K  [C_0402]  271.21 60.23 270 bottom
CA8  0.1U_0402_16V7K~N  [C_0402]  276.21 57.26 180 bottom
CA9  0.1U_0402_10V7K  [C_0402]  279.39 58.5 270 top
CA10  10U_0603_10V6M  [C_0603]  280.45 57.67 90 top
CA11  10U_0603_10V6M  [C_0603]  281.64 59.14 90 top
CA12  0.1U_0402_10V7K  [C_0402]  277.51 66.2 90 bottom
CA13  10U_0603_6.3V6M~D  [C_0603]  279.83 66.86 180 top
CA14  10U_0603_6.3V6M~D  [C_0603]  274.06 67.02 270 top
CA15  0.1U_0402_10V7K  [C_0402]  275.6 65.89 90 top
CA16  0.1U_0402_10V7K  [C_0402]  278.6 61.17 0 top
CA17  100P_0402_50V8J  [C_0402]  270.12 60.2 270 bottom
CA18  100P_0402_50V8J~D  [C_0402]  277.56 61.02 270 top
CA19  2.2U_0603_6.3V6K~D  [C_0603]  280.04 66.4 180 bottom
CA20  0.1U_0402_10V7K  [C_0402]  273.47 57.21 0 bottom
CA21  47P_0402_50V8J~D  [C_0402]  274.66 66.2 90 bottom
CA22  100P_0402_50V8J  [C_0402]  275.27 55.43 90 bottom
CA23  10U_0402_6.3V6M  [C_0402]  282.35 60.05 0 bottom
CA24  2.2U_0402_6.3V6M  [C_0402]  282.42 56.6 0 bottom
CA25  10U_0603_6.3V6M~D  [C_0603]  279.86 65.64 180 top
CA26  10U_0603_6.3V6M~D  [C_0603]  279.76 56.42 0 bottom
CA27  10U_0603_6.3V6M~D  [C_0603]  275.76 63.58 90 top
CA28  10P_0201_25V9  [C_0201]  272.84 56.33 270 top
CA29  10P_0201_25V9  [C_0201]  271.74 56.36 270 top
CA30  2.2U_0603_6.3V6K~D  [C_0603]  281.85 66.48 0 bottom
CA31  330P_0402_50V7K  [C_0402]  282.39 65.44 0 bottom
CA32  330P_0402_50V7K  [C_0402]  282.39 64.55 0 bottom
CA33  33P_0402_50V8J  [C_0402]  271.18 63.49 180 bottom
CA34  33P_0402_50V8J  [C_0402]  269.34 64.38 180 bottom
CA35  33P_0402_50V8J  [C_0402]  269.33 65.28 180 bottom
CA36  33P_0402_50V8J  [C_0402]  269.33 66.17 180 bottom
CA37  33P_0402_50V8J  [C_0402]  269.33 67.06 180 bottom
CA38  10U_0603_25V6M  [C_0603]  270.47 3.44 270 bottom
CA39  10U_0603_25V6M  [C_0603]  271.67 3.45 270 bottom
CA40  0.1U_0402_25V6K~D  [C_0402]  268.21 2.78 180 bottom
CA41  1000P_0402_25V8J  [C_0402]  268.2 3.68 180 bottom
CA42  0.1U_0402_25V6K~D  [C_0402]  272.81 3.64 270 top
CA43  10U_0603_25V6M  [C_0603]  271.77 3.56 270 top
CA44  10U_0603_25V6M  [C_0603]  274.89 9.3 180 bottom
CA45  0.1U_0402_25V6K~D  [C_0402]  276.22 8.74 0 bottom
CA46  1000P_0402_25V8J  [C_0402]  272.71 3.08 270 bottom
CA47  0.1U_0201_6.3V6K  [C_0201]  266.69 10.34 180 bottom
CA48  1U_0201_6.3V6M  [C_0201]  266.69 9.76 180 bottom
CA49  0.1U_0402_16V7K~N  [C_0402]  268.73 12.24 0 bottom
CA50  10U_0603_25V6M  [C_0603]  274.89 10.57 180 bottom
CA51  0.1U_0402_25V6K~D  [C_0402]  276.25 10.5 0 bottom
CA52  1000P_0402_25V8J  [C_0402]  276.22 9.62 0 bottom
CA53  1U_0201_6.3V6M  [C_0201]  268.92 11.51 0 bottom
CA54  1U_0603_25V6  [C_0603]  274.04 3.84 0 top
CA55  0.1U_0402_16V7K~N  [C_0402]  266.93 12.03 90 bottom
CA56  1U_0201_6.3V6M  [C_0201]  267.69 12.1 90 bottom
CA57  1U_0603_25V6  [C_0603]  275.78 14.61 0 top
CA58  10U_0603_25V6M  [C_0603]  274.89 13.11 180 bottom
CA59  10U_0603_25V6M  [C_0603]  274.89 11.89 180 bottom
CA60  0.1U_0402_25V6K~D  [C_0402]  274.45 14.18 180 bottom
CA61  1000P_0402_25V8J  [C_0402]  276.26 11.39 0 bottom
CA62  0.22U 25V K X5R  [C_0402]  277.51 11.75 90 top
CA63  0.22U 25V K X5R  [C_0402]  278.37 10.28 270 top
CA64  0.22U 25V K X5R  [C_0402]  278.38 7.55 90 top
CA65  0.22U 25V K X5R  [C_0402]  277.33 5.49 270 top
CA66  10U_0402_6.3V6M  [C_0402]  267.12 1.68 90 top
CA67  0.1U_0402_25V6K~D  [C_0402]  268.01 2.6 270 top
CA68  330P_0201_50V7K  [C_0201]  278.46 12.67 0 top
CA69  330P_0201_50V7K  [C_0201]  279.15 8.98 0 top
CA70  330P_0201_50V7K  [C_0201]  279.16 6.83 270 top
CA71  330P_0201_50V7K  [C_0201]  278.3 4.51 0 top
CA72  680P_0402_50V7K~D  [C_0402]  280 12 270 top
CA73  680P_0402_50V7K~D  [C_0402]  280.88 10.16 90 top
CA74  680P_0402_50V7K~D  [C_0402]  280.83 7.79 270 top
CA75  680P_0402_50V7K~D  [C_0402]  279.81 5.33 270 top
CA76  680P_0402_50V7K~D  [C_0402]  287.86 64.36 270 bottom
CA77  680P_0402_50V7K~D  [C_0402]  287.4 61.19 90 bottom
CA78  680P_0402_50V7K~D  [C_0402]  286.52 60.33 0 bottom
CA79  680P_0402_50V7K~D  [C_0402]  291.78 69.25 180 bottom
CA80  10U_0603_6.3V6M  [C_0603]  282.43 57.74 0 bottom
CA81  10U_0603_6.3V6M  [C_0603]  282.43 59.01 0 bottom
CA82  4.7U_0402_6.3V6M  [C_0402]  167.05 15.76 270 bottom
CA83  10P_0201_25V9  [C_0201]  274.49 57.02 270 top
CC2  12P_0402_50V8J  [C_0402]  136.36 38.82 90 bottom
CC4  0.1U_0402_25V6  [C_0402]  166.04 41.04 0 bottom
CC5  33P_0402_50V8J  [C_0402]  168.44 40.1 270 bottom
CC6  15P_0402_50V8J  [C_0402]  117.54 69.09 180 bottom
CC7  15P_0402_50V8J  [C_0402]  119.27 69.12 0 bottom
CC8  6.8P_0402_50V8J  [C_0402]  137.97 37.99 0 top
CC9  1U_0402_6.3V6K  [C_0402]  132.61 38.76 90 top
CC10  6.8P_0402_50V8J  [C_0402]  137.09 37.99 180 top
CC11  1U_0402_6.3V6K  [C_0402]  150.08 39 90 bottom
CC12  0.01U_0402_16V7K  [C_0402]  129.36 39.73 270 bottom
CC13  22P_0402_50V8J  [C_0402]  126.5 39.78 270 bottom
CC19  10U_0402_6.3V6M  [C_0402]  104.13 56.7 0 top
CC20  1U_0201_6.3V6M  [C_0201]  102.31 57.93 180 top
CC21  1U_0201_6.3V6M  [C_0201]  102.31 57.36 180 top
CC22  1U_0201_6.3V6M  [C_0201]  103.68 57.56 0 top
CC23  1U_0201_6.3V6M  [C_0201]  103.68 58.13 0 top
CC24  1U_0201_6.3V6M  [C_0201]  102.31 56.79 180 top
CC25  1U_0201_6.3V6M  [C_0201]  103.67 58.73 0 top
CC26  10U_0402_6.3V6M  [C_0402]  102.43 53.42 180 top
CC27  10U_0402_6.3V6M  [C_0402]  104.31 55.33 0 top
CC28  1U_0402_6.3V6K  [C_0402]  127.28 66.26 270 top
CC29  1U_0402_6.3V6K  [C_0402]  124.3 66.58 270 top
CC30  1U_0201_6.3V6M  [C_0201]  124.75 51.52 0 top
CC31  1U_0402_6.3V6K  [C_0402]  124.49 60.8 270 top
CC32  22U_0603_6.3V6M  [C_0603]  113.44 41.3 270 top
CC33  22U_0603_6.3V6M  [C_0603]  120.12 42.19 270 top
CC34  22U_0603_6.3V6M  [C_0603]  111.66 41.97 270 top
CC35  10U_0402_6.3V6M  [C_0402]  115.47 43.14 90 top
CC36  10U_0402_6.3V6M  [C_0402]  119.79 43.7 90 top
CC37  10U_0402_6.3V6M  [C_0402]  123.98 43.57 90 top
CC38  10U_0402_6.3V6M  [C_0402]  113.82 45.63 270 top
CC39  1U_0402_6.3V6K  [C_0402]  122.21 52.52 90 top
CC40  1U_0402_6.3V6K  [C_0402]  113.56 51.27 90 top
CC41  1U_0402_6.3V6K  [C_0402]  120.44 52.52 90 top
CC42  1U_0402_6.3V6K  [C_0402]  119.55 52.52 90 top
CC43  10U_0402_6.3V6M  [C_0402]  112.17 43.76 90 top
CC44  1U_0201_6.3V6M  [C_0201]  117.1 46.44 270 top
CC45  10U_0402_6.3V6M  [C_0402]  120.68 43.7 90 top
CC46  10U_0402_6.3V6M  [C_0402]  108.98 43.62 90 top
CC47  1U_0201_6.3V6M  [C_0201]  111.06 43.85 90 top
CC48  1U_0201_6.3V6M  [C_0201]  120.74 46.47 270 top
CC49  1U_0201_6.3V6M  [C_0201]  113.06 46.44 270 top
CC50  1U_0201_6.3V6M  [C_0201]  123.47 46.44 270 top
CC51  10U_0402_6.3V6M  [C_0402]  114.44 51.25 90 top
CC52  10U_0402_6.3V6M  [C_0402]  121.32 52.52 90 top
CC53  1U_0201_6.3V6M  [C_0201]  120.36 50.51 180 top
CC54  1U_0201_6.3V6M  [C_0201]  114.07 50.13 180 top
CC55  1U_0201_6.3V6M  [C_0201]  120.42 51.65 180 top
CC56  1U_0201_6.3V6M  [C_0201]  121.44 50.38 0 top
CC57  1U_0402_6.3V6K  [C_0402]  129.82 52.79 180 top
CC58  1U_0402_6.3V6K  [C_0402]  128.47 56.35 0 top
CC59  1U_0402_6.3V6K  [C_0402]  130.25 56.35 0 top
CC60  47U_0603_6.3V  [C_0603]  151.93 42.76 270 bottom
CC61  47U_0603_6.3V  [C_0603]  149.56 52.41 0 bottom
CC62  47U_0603_6.3V  [C_0603]  125.45 72.73 0 bottom
CC63  47U_0603_6.3V  [C_0603]  148.67 58 0 bottom
CC64  1U_0402_6.3V6K  [C_0402]  127.8 59.6 270 top
CC65  1U_0402_6.3V6K  [C_0402]  137.06 48.78 90 top
CC66  1U_0402_6.3V6K  [C_0402]  127.79 54.45 0 top
CC67  1U_0402_6.3V6K  [C_0402]  126.79 55.33 0 top
CC68  4.7P_0402_50V8C  [C_0402]  125.88 56.22 270 top
CC69  1U_0402_6.3V6K  [C_0402]  141.12 54.7 0 bottom
CC70  47U_0603_6.3V  [C_0603]  130.02 72.73 180 bottom
CC71  1U_0402_6.3V6K  [C_0402]  130.46 58.76 0 top
CC72  0.1U_0402_10V7K  [C_0402]  129.99 43.42 90 top
CC73  1U_0402_6.3V6K  [C_0402]  130.87 43.42 90 top
CC74  0.1U_0402_10V7K  [C_0402]  127.41 51.91 90 top
CC75  1U_0402_6.3V6K  [C_0402]  128.65 50.33 0 top
CC76  0.1U_0402_10V7K  [C_0402]  132 45 135 top
CC77  2.2P_0201_25V  [C_0201]  125.93 50.88 90 top
CC78  1U_0402_6.3V6K  [C_0402]  125.63 52.67 0 top
CC79  1U_0402_6.3V6K  [C_0402]  126.52 57.68 180 top
CC80  1U_0402_6.3V6K  [C_0402]  130.63 61.09 180 top
CC81  22U_0603_6.3V6M  [C_0603]  141.04 38.18 270 top
CC82  22U_0603_6.3V6M  [C_0603]  139.6 39.03 180 top
CC83  1U_0402_6.3V6K  [C_0402]  132.23 65.19 270 top
CC85  0.1U_0201_10V6K  [C_0201]  40.32 67.46 0 top
CC86  0.1U_0201_10V6K  [C_0201]  39.7 67.46 180 top
CC87  0.1U_0201_10V6K  [C_0201]  38.39 67.49 270 top
CC88  0.1U_0201_10V6K  [C_0201]  42.48 67.46 0 top
CC89  0.1U_0402_25V6  [C_0402]  33.33 70.36 270 top
CC90  15P_0402_50V8J  [C_0402]  143.42 62.5 90 bottom
CC91  15P_0402_50V8J  [C_0402]  143.45 61.63 270 bottom
CC92  0.1U_0402_10V7K  [C_0402]  117.9 14.18 270 bottom
CC93  0.1U 16V K X5R 0201  [C_0201]  130.95 39.26 90 bottom
CC94  0.1U_0402_10V7K  [C_0402]  127.8 51.09 270 top
CC95  2.2P_0201_25V  [C_0201]  124.37 50.88 0 top
CC96  0.1U_0402_10V7K  [C_0402]  126.4 66.28 270 top
CC97  0.1U_0402_10V7K  [C_0402]  100.29 71.91 0 top
CD1  1U_0402_6.3V6K~D  [C_0402]  132.51 21.74 90 top
CD2  10U_0603_6.3V6M~D  [C_0603]  81.95 24.4 90 top
CD3  1U_0402_6.3V6K~D  [C_0402]  132.49 20.54 270 top
CD4  10U_0603_6.3V6M~D  [C_0603]  113.88 18.08 0 top
CD5  1U_0402_6.3V6K~D  [C_0402]  89.87 15.77 270 top
CD6  10U_0603_6.3V6M~D  [C_0603]  132.95 14.82 0 bottom
CD7  1U_0402_6.3V6K~D  [C_0402]  90.76 15.77 270 top
CD8  1U_0402_6.3V6K~D  [C_0402]  118.99 30.44 180 top
CD9  10U_0603_6.3V6M~D  [C_0603]  148.41 23.13 270 top
CD10  1U_0402_6.3V6K~D  [C_0402]  132.49 25.62 90 top
CD11  1U_0402_6.3V6K~D  [C_0402]  148.31 18.02 90 top
CD12  1U_0402_6.3V6K~D  [C_0402]  148.31 25.77 90 top
CD13  1U_0402_6.3V6K~D  [C_0402]  113.51 30.26 90 top
CD14  1U_0402_6.3V6K~D  [C_0402]  143.37 14.94 180 bottom
CD15  10U_0603_6.3V6M~D  [C_0603]  95.27 30.46 180 top
CD16  1U_0402_6.3V6K~D  [C_0402]  138.77 14.94 0 bottom
CD17  1U_0402_6.3V6K~D  [C_0402]  100 30.34 0 top
CD18  1U_0402_6.3V6K~D  [C_0402]  97.11 23.71 90 top
CD19  1U_0402_6.3V6K~D  [C_0402]  107.49 30.34 0 top
CD20  0.1U_0402_16V7K~D  [C_0402]  123.08 30.34 180 top
CD21  0.1U_0402_16V7K~D  [C_0402]  132.49 27.78 90 top
CD22  10U_0603_6.3V6M~D  [C_0603]  84.53 30.42 180 top
CD23  1U_0402_6.3V6K~D  [C_0402]  103.04 30.34 180 top
CD24  1U_0402_6.3V6K~D  [C_0402]  120.93 30.34 180 top
CD25  1U_0402_6.3V6K~D  [C_0402]  106.55 30.31 90 top
CD26  1U_0402_6.3V6K~D  [C_0402]  126.89 30.34 0 top
CD27  0.1U_0402_16V7K~D  [C_0402]  98.12 28.03 90 top
CD28  0.1U_0402_16V7K~D  [C_0402]  112.82 18.4 90 top
CD29  10U_0603_6.3V6M~D  [C_0603]  82.32 23.1 180 top
CD30  1U_0402_6.3V6K~D  [C_0402]  133.5 26.63 270 top
CD31  1U_0402_6.3V6K~D  [C_0402]  85.49 30.34 0 top
CD32  10U_0603_6.3V6M~D  [C_0603]  122.21 14.88 270 bottom
CD33  1U_0402_6.3V6K~D  [C_0402]  135.73 30.34 0 top
CD34  1U_0402_6.3V6K~D  [C_0402]  82.41 26.75 180 top
CD35  0.047U_0402_10V7K~D  [C_0402]  105.2 30.34 180 top
CD36  0.047U_0402_10V7K~D  [C_0402]  140.68 14.94 0 bottom
CD37  0.047U_0402_10V7K~D  [C_0402]  90.32 30.32 180 top
CD38  0.047U_0402_10V7K~D  [C_0402]  125.21 14.94 180 bottom
CD39  10U_0603_6.3V6M~D  [C_0603]  143.09 30.41 180 top
CD40  10U_0603_6.3V6M~D  [C_0603]  117.77 20.47 90 top
CD41  1U_0402_6.3V6K~D  [C_0402]  97.99 21.68 90 top
CD42  1U_0402_6.3V6K~D  [C_0402]  82.19 20.56 180 top
CD43  10U_0603_6.3V6M~D  [C_0603]  110.92 30.46 180 top
CD44  10U_0603_6.3V6M~D  [C_0603]  112.94 21.61 270 top
CD45  1U_0402_6.3V6K~D  [C_0402]  97.11 20.16 270 top
CD46  1U_0402_6.3V6K~D  [C_0402]  112.82 17.51 270 top
CD47  10U_0603_6.3V6M~D  [C_0603]  82.32 21.7 180 top
CD48  1U_0402_6.3V6K~D  [C_0402]  98.12 25.87 90 top
CD49  1U_0402_6.3V6K~D  [C_0402]  132.55 17.62 90 top
CD50  1U_0402_6.3V6K~D  [C_0402]  113.53 22.66 90 top
CD51  10U_0603_6.3V6M~D  [C_0603]  82.21 27.71 90 top
CD52  1U_0402_6.3V6K~D  [C_0402]  117.9 28.58 90 top
CD53  1U_0402_6.3V6K~D  [C_0402]  117.9 22.99 90 top
CD54  1U_0402_6.3V6K~D  [C_0402]  112.62 30.21 90 top
CD55  10U_0603_6.3V6M~D  [C_0603]  144.5 14.82 0 bottom
CD56  1U_0402_6.3V6K~D  [C_0402]  112.65 22.64 90 top
CD57  1U_0402_6.3V6K~D  [C_0402]  127.24 14.94 180 bottom
CD58  1U_0402_6.3V6K~D  [C_0402]  97.11 28.03 90 top
CD59  1U_0402_6.3V6K~D  [C_0402]  97.11 25.87 90 top
CD60  0.1U_0402_16V7K~D  [C_0402]  82.19 18.65 180 top
CD61  0.1U_0402_16V7K~D  [C_0402]  88.41 30.34 180 top
CD62  10U_0603_6.3V6M~D  [C_0603]  137.64 14.82 180 bottom
CD63  1U_0402_6.3V6K~D  [C_0402]  91.84 30.34 0 top
CD64  1U_0402_6.3V6K~D  [C_0402]  98.12 23.71 90 top
CD65  1U_0402_6.3V6K~D  [C_0402]  120.77 14.94 180 bottom
CD66  1U_0402_6.3V6K~D  [C_0402]  148.31 24.01 90 top
CD67  0.1U_0402_16V7K~D  [C_0402]  148.31 27.52 90 top
CD68  0.1U_0402_16V7K~D  [C_0402]  133.5 28.66 270 top
CD69  10U_0603_6.3V6M~D  [C_0603]  97.89 31.26 270 top
CD70  1U_0402_6.3V6K~D  [C_0402]  143.98 30.24 0 top
CD71  1U_0402_6.3V6K~D  [C_0402]  138.65 30.34 180 top
CD72  10U_0603_6.3V6M~D  [C_0603]  130.45 30.46 180 top
CD73  1U_0402_6.3V6K~D  [C_0402]  133.5 23.84 90 top
CD74  1U_0402_6.3V6K~D  [C_0402]  132.49 23.71 90 top
CD75  0.047U_0402_10V7K~D  [C_0402]  140.81 30.34 180 top
CD76  0.047U_0402_10V7K~D  [C_0402]  110 15.26 270 top
CD77  0.047U_0402_10V7K~D  [C_0402]  125.24 30.34 180 top
CD78  0.047U_0402_10V7K~D  [C_0402]  88.98 15.77 270 top
CD79  0.022U_0402_16V7K~D  [C_0402]  99.9 37.26 180 top
CD80  0.022U_0402_16V7K~D  [C_0402]  88.47 34.85 180 top
CD81  0.022U_0402_16V7K~D  [C_0402]  91.17 34.9 270 top
CD92  0.22U_0402_10V6K  [C_0402]  163.63 19.9 180 bottom
CD93  0.22U_0402_10V6K  [C_0402]  163.63 20.78 180 bottom
CD94  0.22U_0402_10V6K  [C_0402]  163.63 22.56 180 bottom
CD95  0.22U_0402_10V6K  [C_0402]  163.63 23.45 180 bottom
CD96  0.22U_0402_10V6K  [C_0402]  163.63 24.34 180 bottom
CD97  0.22U_0402_10V6K  [C_0402]  163.63 25.23 180 bottom
CD98  0.22U_0402_10V6K  [C_0402]  157.46 40.04 270 bottom
CD99  0.22U_0402_10V6K  [C_0402]  158.35 40.04 270 bottom
CD100  1U_0402_6.3V6K~D  [C_0402]  85.49 14.56 270 top
CD101  1U_0402_6.3V6K~D  [C_0402]  93.45 15.3 90 top
CD102  1U_0402_6.3V6K~D  [C_0402]  108.12 14.6 0 top
CD103  1U_0402_6.3V6K~D  [C_0402]  101.74 14.36 270 top
CD104  22U_0603_6.3V6M~D  [C_0603]  94.53 14.75 90 top
CD105  1U_0402_6.3V6K~D  [C_0402]  118.18 14.89 270 top
CD106  1U_0402_6.3V6K~D  [C_0402]  119.8 14.89 270 top
CD107  1U_0402_6.3V6K~D  [C_0402]  136.96 15.01 90 top
CD108  1U_0402_6.3V6K~D  [C_0402]  145.84 15.72 0 top
CD109  22U_0603_6.3V6M~D  [C_0603]  116.44 16.86 180 top
CE42  0.1U_0201_10V6K  [C_0201]  23.69 11.07 90 bottom
CE43  0.1U_0201_10V6K  [C_0201]  24.3 17.32 90 bottom
CE44  1U_0402_6.3V6K  [C_0402]  19.75 7.17 0 top
CE45  0.1U_0201_10V6K  [C_0201]  20.22 7.92 0 top
CE46  10U_0603_6.3V6M  [C_0603]  30.49 16.96 90 top
CE47  22U_0603_6.3V6M  [C_0603]  27.73 13.55 90 top
CE48  0.1U_0201_10V6K  [C_0201]  26.84 13.66 90 top
CE49  0.1U_0201_10V6K  [C_0201]  26.81 15.49 270 top
CE50  0.1U_0201_10V6K  [C_0201]  17.15 21.83 180 top
CE51  0.1U_0201_10V6K  [C_0201]  10.45 17.36 90 bottom
CE52  12P_0402_50V8J  [C_0402]  18.43 4.78 180 top
CE53  68P_0402_50V8J  [C_0402]  18.43 5.7 180 top
CE54  0.1U_0201_10V6K  [C_0201]  25.36 23.08 270 top
CE55  0.1U_0201_10V6K  [C_0201]  22.35 21.67 180 top
CE56  0.1U_0201_10V6K  [C_0201]  12.99 18.69 90 top
CE57  10P_0402_50V8J  [C_0402]  24.17 14.31 90 bottom
CE58  2200P_0402_50V7K  [C_0402]  18.51 7.8 270 top
CE59  2200P_0402_50V7K  [C_0402]  16.25 7.83 270 top
CE60  2200P_0402_50V7K  [C_0402]  27.29 19.55 0 bottom
CE61  2200P_0402_50V7K  [C_0402]  29.4 20.47 0 top
CE62  2200P_0402_50V7K  [C_0402]  15.1 7.83 270 top
CE63  1U_0402_6.3V6K  [C_0402]  11.66 13.49 270 top
CE64  1U_0402_6.3V6K  [C_0402]  27.52 16.78 0 top
CE65  33P_0402_50V8J  [C_0402]  31.05 12.33 90 top
CE66  12P_0402_50V8J  [C_0402]  24.7 7.78 0 top
CE67  12P_0402_50V8J  [C_0402]  23.76 6.86 180 top
CE68  1U_0402_6.3V6K  [C_0402]  27.43 7.8 270 bottom
CE69  2.2U_0402_6.3V6M  [C_0402]  24.74 7.78 270 bottom
CE70  0.1U_0402_25V6K  [C_0402]  5.02 23.49 270 bottom
CE72  68P_0402_50V8J  [C_0402]  5.91 23.49 270 bottom
CE73  0.1U_0402_25V6K  [C_0402]  3.99 24.47 180 bottom
CE75  4700P_0402_25V7K  [C_0402]  12.56 16.15 180 top
CE76  4700P_0402_25V7K  [C_0402]  12.56 17.93 180 bottom
CE78  4700P_0402_25V7K  [C_0402]  29.99 13.61 0 bottom
CE79  0.1U_0402_25V6  [C_0402]  12.44 6.99 180 top
CE83  100P_0402_50V8J  [C_0402]  121.76 56.09 270 top
CE84  2.2P_0201_25V  [C_0201]  141.85 53.42 180 top
CE86  0.1U_0402_25V6  [C_0402]  27.14 19.39 0 top
CE87  100P_0402_50V8J  [C_0402]  133.26 7.45 0 top
CE89  100P_0402_50V8J  [C_0402]  285.99 41.83 90 bottom
CE90  2200P_0402_50V7K  [C_0402]  17.36 7.83 270 top
CE91  100P_0402_50V8J  [C_0402]  161.83 14.68 180 bottom
CE93  100P_0402_50V8J  [C_0402]  70.78 5.4 180 bottom
CE94  100P_0402_50V8J  [C_0402]  167.96 70.37 0 top
CE95  100P_0402_50V8J  [C_0402]  143.32 71.11 0 top
CE96  2.2P_0201_25V  [C_0201]  142.53 54.1 270 top
CH1  0.1U_0402_10V7K~D  [C_0402]  281.78 47.64 45 top
CH2  0.1U_0402_10V7K~D  [C_0402]  282.42 47 45 top
CH3  1U_0402_6.3V6K  [C_0402]  219.34 14.5 270 bottom
CH4  0.1U_0402_10V7K~D  [C_0402]  281.27 45.93 0 top
CH5  0.1U_0402_10V7K~D  [C_0402]  281.27 45.04 0 top
CLRP1  SHORT PADS  [SHORTPADS]  252.71 11.91 90 bottom
CMOS1  SHORT PADS~D  [SHORTPADS]  151.17 39.58 90 bottom
CR1  10U_0402_6.3V6M  [C_0402]  280.11 32.91 180 top
CR2  0.1U_0201_10V6K  [C_0201]  280.18 32.15 180 top
CR3  4.7U_0402_6.3V6M  [C_0402]  294.54 34 270 bottom
CR4  0.1U_0201_10V6K  [C_0201]  294.73 35.68 90 bottom
CR5  0.1U_0201_10V6K  [C_0201]  292.46 34.41 0 bottom
CR6  4.7U_0402_6.3V6M  [C_0402]  292.57 35.14 0 bottom
CR7  10U_0402_6.3V6M  [C_0402]  292.53 36.06 0 bottom
CR8  0.1U_0201_10V6K  [C_0201]  283.95 32.85 180 bottom
CR9  1U_0201_6.3V6M  [C_0201]  287.31 37.84 270 bottom
CR10  0.1U_0201_10V6K  [C_0201]  287.57 29.84 90 bottom
CR11  0.1U_0201_10V6K  [C_0201]  286.93 29.84 90 bottom
CR17  2.2P_0402_50V8C  [C_0402]  285.92 37.29 90 bottom
CR18  0.1U_0201_10V6K  [C_0201]  284.1 32.18 0 bottom
CR19  0.1U_0201_10V6K  [C_0201]  284.68 31.6 180 bottom
CR20  1U_0201_6.3V6M  [C_0201]  289.92 37.79 270 bottom
CR21  4.7U_0402_6.3V6M  [C_0402]  284.72 35.31 180 bottom
CR22  0.1U_0201_10V6K  [C_0201]  288.52 29.84 90 bottom
CR23  0.1U_0201_10V6K  [C_0201]  289.16 29.84 90 bottom
CR24  2.2P_0201_25V  [C_0201]  126.91 40.85 270 top
CR25  2.2P_0201_25V  [C_0201]  126.78 40.49 0 bottom
CR26  2.2P_0201_25V  [C_0201]  125.18 38.71 0 bottom
CT1  0.22U_0201_6.3V6M  [C_0201]  28.17 40.71 270 bottom
CT2  0.22U_0201_6.3V6M  [C_0201]  26.9 40.12 90 bottom
CT3  0.22U_0201_6.3V6M  [C_0201]  28.8 40.71 270 bottom
CT4  0.22U_0201_6.3V6M  [C_0201]  27.53 40.12 90 bottom
CT5  0.22U_0201_6.3V6M  [C_0201]  25.5 40.71 270 bottom
CT6  0.22U_0201_6.3V6M  [C_0201]  22.48 40.11 90 bottom
CT7  0.22U_0201_6.3V6M  [C_0201]  23.06 40.7 270 bottom
CT8  0.22U_0201_6.3V6M  [C_0201]  21.89 40.11 90 bottom
CT9  0.22U_0201_6.3V6M  [C_0201]  21.31 40.71 270 bottom
CT10  0.22U_0201_6.3V6M  [C_0201]  20.14 40.12 90 bottom
CT11  0.22U_0201_6.3V6M  [C_0201]  20.72 40.71 270 bottom
CT12  0.22U_0201_6.3V6M  [C_0201]  19.55 40.12 90 bottom
CT13  0.1U_0201_6.3V6K  [C_0201]  30.03 50.07 0 bottom
CT14  0.1U_0201_6.3V6K  [C_0201]  30.03 49.43 0 bottom
CT15  0.1U_0201_6.3V6K  [C_0201]  31.79 48.34 0 bottom
CT16  0.1U_0201_6.3V6K  [C_0201]  30.03 48.29 0 bottom
CT17  0.1U_0201_6.3V6K  [C_0201]  31.79 47.07 0 bottom
CT18  0.1U_0201_6.3V6K  [C_0201]  31.79 46.44 0 bottom
CT19  0.22U_0201_6.3V6M  [C_0201]  24.86 40.12 90 bottom
CT20  0.22U_0201_6.3V6M  [C_0201]  26.13 40.71 270 bottom
CT21  0.22U_0201_6.3V6M  [C_0201]  24.23 40.12 90 bottom
CT22  0.22U_0201_6.3V6M  [C_0201]  23.64 40.7 270 bottom
CT23  0.1U_0201_6.3V6K  [C_0201]  31.79 48.98 0 bottom
CT24  0.1U_0201_6.3V6K  [C_0201]  30.03 47.65 0 bottom
CT25  0.1U_0201_6.3V6K  [C_0201]  31.79 51.65 0 bottom
CT26  0.1U_0201_6.3V6K  [C_0201]  31.79 52.28 0 bottom
CT27  0.1U_0201_6.3V6K  [C_0201]  30.03 46.51 0 bottom
CT28  0.1U_0201_6.3V6K  [C_0201]  30.03 45.88 0 bottom
CT29  0.1U_0201_6.3V6K  [C_0201]  31.79 45.68 0 bottom
CT30  0.1U_0201_6.3V6K  [C_0201]  31.79 45.04 0 bottom
CT31  0.1U_0201_6.3V6K  [C_0201]  30.03 44.86 0 bottom
